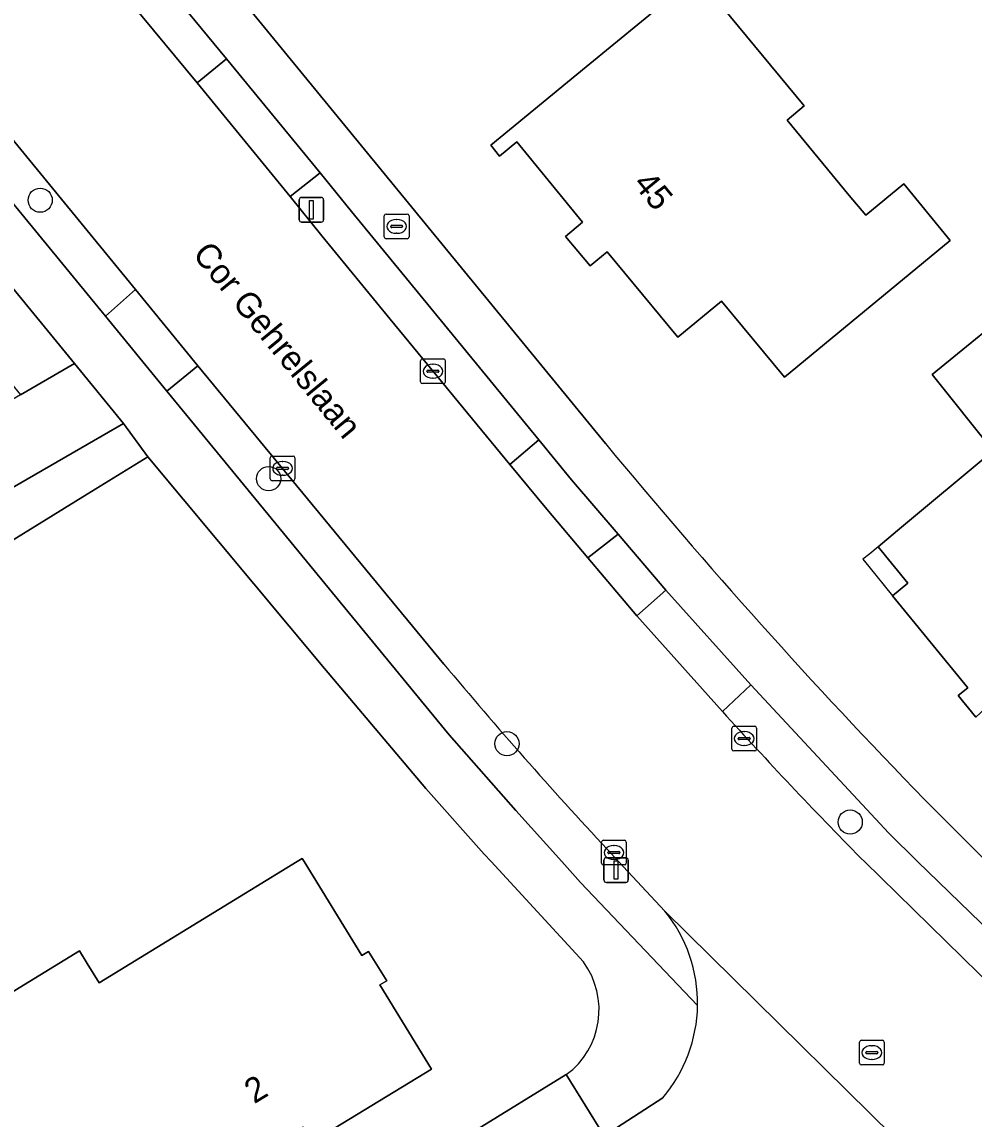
# Model space of a CAD drawing. Extents: x 157320 to 158835, y 386650 to 388491.
# Drawn here: x 157997.35 to 158035.89, y 387239.59 to 387283.97 of the extents above; entities that cross this region are included whole.
import ezdxf

# ---------------------------------------------------------------- set-up
doc = ezdxf.new("R2010")
doc.units = 0
for name, color, linetype in [('IMGEO_Boom', 7, 'Continuous'), ('IMGEO_Brandkraan', 7, 'Continuous'), ('IMGEO_Erf', 7, 'Continuous'), ('IMGEO_Groenvoorziening', 7, 'Continuous'), ('IMGEO_Kolk', 7, 'Continuous'), ('IMGEO_Lichtmast', 7, 'Continuous'), ('IMGEO_Openbare_ruimte_label', 7, 'Continuous'), ('IMGEO_Pand', 7, 'Continuous'), ('IMGEO_Pand_nummerreeks', 7, 'Continuous'), ('IMGEO_Pand_overbouw', 7, 'Continuous'), ('IMGEO_Rijbaan_lokaal_gesloten', 7, 'Continuous'), ('IMGEO_Rioolput', 7, 'Continuous'), ('IMGEO_Voetpad_open', 7, 'Continuous')]:
    doc.layers.add(name, color=color, linetype=linetype)

msp = doc.modelspace()

# ---------------------------------------------------------------- linework, layer by layer
at = {"layer": 'IMGEO_Boom'}
for centre in [(157998.093, 387276.755), (158007.337, 387265.491), (158016.984, 387254.77), (158030.877, 387251.601)]:
    msp.add_circle(centre, 0.489, dxfattribs=at)
at = {"layer": 'IMGEO_Brandkraan'}
for p, q in [((158012.02, 387275.27), (158012.02, 387276.122)), ((158012.095, 387276.196), (158012.947, 387276.196)), ((158012.508, 387275.976), (158012.533, 387275.976)), ((158013.021, 387276.122), (158013.021, 387275.27)), ((158012.279, 387275.69), (158012.279, 387275.702)), ((158012.717, 387275.653), (158012.319, 387275.653)), ((158012.322, 387275.739), (158012.72, 387275.739)), ((158012.763, 387275.702), (158012.763, 387275.69)), ((158012.947, 387275.196), (158012.095, 387275.196)), ((158012.531, 387275.416), (158012.506, 387275.416))]:
    msp.add_line(p, q, dxfattribs=at)
for points in [[(158012.02, 387275.27), (158012.02, 387276.122)], [(158012.095, 387276.196), (158012.947, 387276.196)], [(158013.021, 387276.122), (158013.021, 387275.27)], [(158012.947, 387275.196), (158012.095, 387275.196)]]:
    msp.add_lwpolyline(points, dxfattribs=at)
for centre, radius, start, end in [((158012.097, 387276.12), 0.0765, 91.552, 178.448), ((158012.097, 387276.12), 0.0765, 91.552, 178.448), ((158012.945, 387276.12), 0.0765, 1.552, 88.448), ((158012.945, 387276.12), 0.0765, 1.552, 88.448), ((158012.319, 387275.699), 0.0403, 85.8775, 175.7526), ((158012.316, 387275.689), 0.0366, 178.938, 274.7102), ((158012.72, 387275.696), 0.043, 264.8664, 352.4533), ((158012.724, 387275.701), 0.0386, 1.7309, 96.639), ((158012.097, 387275.272), 0.0765, 181.552, 268.448), ((158012.097, 387275.272), 0.0765, 181.552, 268.448), ((158012.945, 387275.272), 0.0765, 271.552, 358.448), ((158012.945, 387275.272), 0.0765, 271.552, 358.448)]:
    msp.add_arc(centre, radius, start, end, dxfattribs=at)
for centre, major_axis, ratio, start_param, end_param in [((158012.507, 387275.696), (-0.387, 0.002), 0.722429, 4.712389, 7.853982), ((158012.532, 387275.696), (-0.39, 0.002), 0.717154, 1.570796, 4.712389)]:
    msp.add_ellipse(centre, major_axis=major_axis, ratio=ratio, start_param=start_param, end_param=end_param, dxfattribs=at)
at = {"layer": 'IMGEO_Erf'}
for points in [[(157999.612, 387292.962), (158000.785, 387291.532), (158020.97, 387266.911)], [(158020.077, 387245.943), (158016.341, 387250), (158016.061, 387250.304), (158013.703, 387252.963), (158009.6, 387257.817), (158002.445, 387266.373), (158000, 387264.864), (157981.765, 387253.617), (157983.035, 387251.532), (157983.087, 387251.564), (157984.044, 387250), (157994.365, 387233.133)], [(158033.883, 387252.507), (158036.396, 387250)], [(158004.318, 387232.11), (158019.387, 387241.383)]]:
    msp.add_lwpolyline(points, dxfattribs=at)
for points in [[(158028.216, 387269.592), (158025.669, 387272.677), (158023.895, 387271.214), (158021.044, 387274.668), (158020.35, 387274.095), (158019.349, 387275.291), (158020.037, 387275.862), (158017.382, 387279.115), (158016.685, 387278.541), (158016.331, 387278.976), (158020.194, 387282.151), (158024.676, 387285.834), (158029.015, 387280.57), (158028.32, 387279.997), (158030.84, 387276.941), (158031.512, 387276.15), (158033.043, 387277.412), (158034.928, 387275.127)], [(158045.536, 387267.864), (158042.435, 387265.326), (158046.172, 387260.759), (158043.755, 387258.784), (158045.209, 387257.004), (158041.925, 387254.321), (158040.47, 387256.101), (158038.045, 387254.121), (158036.328, 387256.186), (158035.96, 387255.846), (158035.247, 387256.719), (158035.633, 387257.035), (158032.594, 387260.758), (158033.211, 387261.262), (158032.006, 387262.738), (158032.794, 387263.394), (158036.658, 387266.612), (158034.188, 387269.705), (158038.068, 387272.86), (158040.106, 387274.518)], [(157993.419, 387242.559), (157999.689, 387246.391), (158000, 387245.882), (158000.476, 387245.103), (158008.489, 387250), (158008.7, 387250.129), (158008.779, 387250), (158011.111, 387246.203), (158011.384, 387246.371), (158012.116, 387245.178), (158011.843, 387245.01), (158013.935, 387241.6), (158009.103, 387238.662), (158008.74, 387239.261), (158006.646, 387237.988), (158007.009, 387237.389), (158002.664, 387234.747), (158000.614, 387238.055), (158000, 387237.679), (157997.381, 387236.076)]]:
    msp.add_lwpolyline(points, close=True, dxfattribs=at)
for centre, radius, start, end in [((158210.543, 387423.871), 246.118, 219.62353, 224.12811), ((158017.451, 387244.008), 3.262, 306.412, 36.3791)]:
    msp.add_arc(centre, radius, start, end, dxfattribs=at)
at = {"layer": 'IMGEO_Groenvoorziening'}
for points in [[(157946.102, 387338.65), (158000, 387272.965), (158000.735, 387272.069), (158001.953, 387273.145), (158000, 387275.528), (157949.905, 387336.66), (157948.052, 387338.921), (157946.867, 387339.91), (157946.189, 387339.362)], [(157998.976, 387288.125), (158000, 387286.885), (158004.449, 387281.5), (158005.629, 387282.478), (158000, 387289.314), (157997.412, 387292.457)], [(158014.434, 387257.989), (158004.474, 387270.061), (158003.224, 387269.036), (158014.64, 387255.124), (158017.345, 387252.062), (158019.205, 387250), (158019.965, 387249.158), (158024.7, 387244.176)], [(158032.44, 387251.155), (158026.857, 387257.158), (158025.703, 387256.074)], [(158031.312, 387250.14), (158031.451, 387250), (158038.073, 387243.529), (158039.142, 387244.637), (158033.601, 387250), (158032.44, 387251.155)], [(158023.38, 387248.001), (158021.505, 387250), (158021.036, 387250.5)]]:
    msp.add_lwpolyline(points, dxfattribs=at)
for points in [[(157956.447, 387322.693), (157954.567, 387321.043), (157995.369, 387271.233), (157997.295, 387268.882), (157999.484, 387270.155)], [(158012.256, 387271.943), (158017.101, 387266.07), (158018.276, 387267.066), (158013.471, 387272.92), (158010.687, 387276.293), (158009.429, 387277.867), (158008.212, 387276.901), (158009.486, 387275.32)], [(158000, 387264.864), (158002.445, 387266.373), (158001.465, 387267.718), (158000, 387266.873), (157981.182, 387256.016), (157970.793, 387250), (157963.952, 387246.039), (157961.785, 387246.252), (157962.166, 387243.986), (157963.282, 387242.2), (157979.287, 387252.079), (157981.765, 387253.617)], [(158022.244, 387259.949), (158023.416, 387260.98), (158021.481, 387263.247), (158020.261, 387262.291)], [(158005.773, 387229.685), (158020.924, 387238.906), (158019.387, 387241.383), (158004.318, 387232.11)]]:
    msp.add_lwpolyline(points, close=True, dxfattribs=at)
for centre, radius, start, end in [((158161.801, 387381.247), 192.119, 219.90923, 222.88697), ((158166.946, 387383.963), 190.539, 222.15946, 224.615), ((158018.783, 387244.274), 5.918, 359.0489, 39.03)]:
    msp.add_arc(centre, radius, start, end, dxfattribs=at)
at = {"layer": 'IMGEO_Kolk'}
for p, q in [((158013.489, 387269.411), (158013.489, 387270.263)), ((158013.564, 387270.337), (158014.416, 387270.337)), ((158014.49, 387270.263), (158014.49, 387269.411)), ((158013.748, 387269.831), (158013.748, 387269.843)), ((158014.186, 387269.794), (158013.788, 387269.794)), ((158013.791, 387269.88), (158014.189, 387269.88)), ((158013.977, 387270.117), (158014.002, 387270.117)), ((158014.232, 387269.843), (158014.232, 387269.831)), ((158014.416, 387269.337), (158013.564, 387269.337)), ((158014, 387269.557), (158013.975, 387269.557)), ((158007.402, 387265.481), (158007.402, 387266.333)), ((158007.477, 387266.407), (158008.329, 387266.407)), ((158007.89, 387266.187), (158007.915, 387266.187)), ((158008.403, 387266.333), (158008.403, 387265.481)), ((158007.661, 387265.901), (158007.661, 387265.913)), ((158008.099, 387265.864), (158007.701, 387265.864)), ((158007.704, 387265.95), (158008.102, 387265.95)), ((158008.145, 387265.913), (158008.145, 387265.901)), ((158008.329, 387265.407), (158007.477, 387265.407)), ((158007.913, 387265.627), (158007.888, 387265.627)), ((158026.086, 387254.553), (158026.086, 387255.405)), ((158026.161, 387255.479), (158027.013, 387255.479)), ((158026.574, 387255.259), (158026.599, 387255.259)), ((158027.087, 387255.405), (158027.087, 387254.553)), ((158026.345, 387254.973), (158026.345, 387254.985)), ((158026.783, 387254.936), (158026.385, 387254.936)), ((158026.388, 387255.022), (158026.786, 387255.022)), ((158026.597, 387254.699), (158026.572, 387254.699)), ((158026.829, 387254.985), (158026.829, 387254.973)), ((158027.013, 387254.479), (158026.161, 387254.479)), ((158020.814, 387249.941), (158020.814, 387250.793)), ((158020.889, 387250.867), (158021.741, 387250.867)), ((158021.302, 387250.647), (158021.327, 387250.647)), ((158021.815, 387250.793), (158021.815, 387249.941)), ((158021.073, 387250.361), (158021.073, 387250.373)), ((158021.511, 387250.324), (158021.113, 387250.324)), ((158021.116, 387250.41), (158021.514, 387250.41)), ((158021.557, 387250.373), (158021.557, 387250.361)), ((158021.741, 387249.867), (158020.889, 387249.867)), ((158021.325, 387250.087), (158021.3, 387250.087))]:
    msp.add_line(p, q, dxfattribs=at)
for points in [[(158013.489, 387269.411), (158013.489, 387270.263)], [(158013.564, 387270.337), (158014.416, 387270.337)], [(158014.49, 387270.263), (158014.49, 387269.411)], [(158014.416, 387269.337), (158013.564, 387269.337)], [(158007.402, 387265.481), (158007.402, 387266.333)], [(158007.477, 387266.407), (158008.329, 387266.407)], [(158008.403, 387266.333), (158008.403, 387265.481)], [(158008.329, 387265.407), (158007.477, 387265.407)], [(158026.086, 387254.553), (158026.086, 387255.405)], [(158026.161, 387255.479), (158027.013, 387255.479)], [(158027.087, 387255.405), (158027.087, 387254.553)], [(158027.013, 387254.479), (158026.161, 387254.479)], [(158020.814, 387249.941), (158020.814, 387250.793)], [(158020.889, 387250.867), (158021.741, 387250.867)], [(158021.815, 387250.793), (158021.815, 387249.941)], [(158021.741, 387249.867), (158020.889, 387249.867)]]:
    msp.add_lwpolyline(points, dxfattribs=at)
for centre, radius, start, end in [((158013.566, 387270.261), 0.0765, 91.552, 178.448), ((158013.566, 387270.261), 0.0765, 91.552, 178.448), ((158014.414, 387270.261), 0.0765, 1.552, 88.448), ((158014.414, 387270.261), 0.0765, 1.552, 88.448), ((158013.788, 387269.84), 0.0403, 85.8775, 175.7526), ((158013.785, 387269.83), 0.0366, 178.938, 274.7102), ((158014.189, 387269.837), 0.043, 264.8664, 352.4533), ((158014.193, 387269.842), 0.0386, 1.7309, 96.639), ((158013.566, 387269.413), 0.0765, 181.552, 268.448), ((158013.566, 387269.413), 0.0765, 181.552, 268.448), ((158014.414, 387269.413), 0.0765, 271.552, 358.448), ((158014.414, 387269.413), 0.0765, 271.552, 358.448), ((158007.479, 387266.331), 0.0765, 91.552, 178.448), ((158007.479, 387266.331), 0.0765, 91.552, 178.448), ((158008.327, 387266.331), 0.0765, 1.552, 88.448), ((158008.327, 387266.331), 0.0765, 1.552, 88.448), ((158007.701, 387265.91), 0.0403, 85.8775, 175.7526), ((158007.698, 387265.9), 0.0366, 178.938, 274.7102), ((158008.102, 387265.907), 0.043, 264.8664, 352.4533), ((158008.106, 387265.912), 0.0386, 1.7309, 96.639), ((158007.479, 387265.483), 0.0765, 181.552, 268.448), ((158007.479, 387265.483), 0.0765, 181.552, 268.448), ((158008.327, 387265.483), 0.0765, 271.552, 358.448), ((158008.327, 387265.483), 0.0765, 271.552, 358.448), ((158026.163, 387255.403), 0.0765, 91.552, 178.448), ((158026.163, 387255.403), 0.0765, 91.552, 178.448), ((158027.011, 387255.403), 0.0765, 1.552, 88.448), ((158027.011, 387255.403), 0.0765, 1.552, 88.448), ((158026.385, 387254.982), 0.0403, 85.8775, 175.7526), ((158026.382, 387254.972), 0.0366, 178.938, 274.7102), ((158026.786, 387254.979), 0.043, 264.8664, 352.4533), ((158026.79, 387254.984), 0.0386, 1.7309, 96.639), ((158026.163, 387254.555), 0.0765, 181.552, 268.448), ((158026.163, 387254.555), 0.0765, 181.552, 268.448), ((158027.011, 387254.555), 0.0765, 271.552, 358.448), ((158027.011, 387254.555), 0.0765, 271.552, 358.448), ((158020.891, 387250.791), 0.0765, 91.552, 178.448), ((158020.891, 387250.791), 0.0765, 91.552, 178.448), ((158021.739, 387250.791), 0.0765, 1.552, 88.448), ((158021.739, 387250.791), 0.0765, 1.552, 88.448), ((158021.113, 387250.37), 0.0403, 85.8775, 175.7526), ((158021.11, 387250.36), 0.0366, 178.938, 274.7102), ((158021.514, 387250.367), 0.043, 264.8664, 352.4533), ((158021.518, 387250.372), 0.0386, 1.7309, 96.639), ((158020.891, 387249.943), 0.0765, 181.552, 268.448), ((158020.891, 387249.943), 0.0765, 181.552, 268.448), ((158021.739, 387249.943), 0.0765, 271.552, 358.448), ((158021.739, 387249.943), 0.0765, 271.552, 358.448)]:
    msp.add_arc(centre, radius, start, end, dxfattribs=at)
for centre, major_axis, ratio, start_param, end_param in [((158013.976, 387269.837), (-0.387, 0.002), 0.722429, 4.712389, 7.853982), ((158014.001, 387269.837), (-0.39, 0.002), 0.717154, 1.570796, 4.712389), ((158007.889, 387265.907), (-0.387, 0.002), 0.722429, 4.712389, 7.853982), ((158007.914, 387265.907), (-0.39, 0.002), 0.717154, 1.570796, 4.712389), ((158026.573, 387254.979), (-0.387, 0.002), 0.722429, 4.712389, 7.853982), ((158026.598, 387254.979), (-0.39, 0.002), 0.717154, 1.570796, 4.712389), ((158021.301, 387250.367), (-0.387, 0.002), 0.722429, 4.712389, 7.853982), ((158021.326, 387250.367), (-0.39, 0.002), 0.717154, 1.570796, 4.712389)]:
    msp.add_ellipse(centre, major_axis=major_axis, ratio=ratio, start_param=start_param, end_param=end_param, dxfattribs=at)
at = {"layer": 'IMGEO_Lichtmast'}
for p, q in [((158008.675, 387276.866), (158009.465, 387276.866)), ((158009.465, 387276.866), (158008.675, 387276.866)), ((158008.575, 387275.966), (158008.575, 387276.766)), ((158008.575, 387276.766), (158008.575, 387275.966)), ((158009.565, 387276.766), (158009.565, 387275.966)), ((158009.565, 387275.966), (158009.565, 387276.766)), ((158009.465, 387275.866), (158008.675, 387275.866)), ((158008.675, 387275.866), (158009.465, 387275.866)), ((158021.007, 387250.16), (158021.797, 387250.16)), ((158021.797, 387250.16), (158021.007, 387250.16)), ((158020.907, 387249.26), (158020.907, 387250.06)), ((158020.907, 387250.06), (158020.907, 387249.26)), ((158021.897, 387250.06), (158021.897, 387249.26)), ((158021.897, 387249.26), (158021.897, 387250.06)), ((158021.797, 387249.16), (158021.007, 387249.16)), ((158021.007, 387249.16), (158021.797, 387249.16))]:
    msp.add_line(p, q, dxfattribs=at)
for points in [[(158008.995, 387276.741), (158009.145, 387276.741), (158009.145, 387275.991), (158008.995, 387275.991), (158008.995, 387276.741)], [(158021.327, 387250.035), (158021.477, 387250.035), (158021.477, 387249.285), (158021.327, 387249.285), (158021.327, 387250.035)]]:
    msp.add_lwpolyline(points, dxfattribs=at)
for centre, start, end in [((158008.675, 387276.766), 90, 180), ((158008.675, 387276.766), 90, 180), ((158009.465, 387276.766), 0, 90), ((158009.465, 387276.766), 360, 90), ((158008.675, 387275.966), 180, 270), ((158008.675, 387275.966), 180, 270), ((158009.465, 387275.966), 270, 0), ((158009.465, 387275.966), 270, 0), ((158021.007, 387250.06), 90, 180), ((158021.007, 387250.06), 90, 180), ((158021.797, 387250.06), 0, 90), ((158021.797, 387250.06), 360, 90), ((158021.007, 387249.26), 180, 270), ((158021.007, 387249.26), 180, 270), ((158021.797, 387249.26), 270, 0), ((158021.797, 387249.26), 270, 0)]:
    msp.add_arc(centre, 0.1, start, end, dxfattribs=at)
at = {"layer": 'IMGEO_Pand'}
for points in [[(158030.84, 387276.941), (158028.32, 387279.997), (158029.015, 387280.57), (158024.676, 387285.834), (158020.194, 387282.151), (158016.331, 387278.976), (158016.685, 387278.541), (158017.382, 387279.115), (158020.037, 387275.862), (158019.349, 387275.291), (158020.35, 387274.095), (158021.044, 387274.668), (158023.895, 387271.214), (158025.669, 387272.677), (158028.216, 387269.592), (158034.928, 387275.127), (158033.043, 387277.412), (158031.512, 387276.15)], [(158045.209, 387257.004), (158043.755, 387258.784), (158046.172, 387260.759), (158042.435, 387265.326), (158045.536, 387267.864), (158040.106, 387274.518), (158038.068, 387272.86), (158034.188, 387269.705), (158036.658, 387266.612), (158032.794, 387263.394), (158032.006, 387262.738), (158033.211, 387261.262), (158032.594, 387260.758), (158035.633, 387257.035), (158035.247, 387256.719), (158035.96, 387255.846), (158036.328, 387256.186), (158038.045, 387254.121), (158040.47, 387256.101), (158041.925, 387254.321)], [(158007.009, 387237.389), (158006.646, 387237.988), (158008.74, 387239.261), (158009.103, 387238.662), (158013.935, 387241.6), (158011.843, 387245.01), (158012.116, 387245.178), (158011.384, 387246.371), (158011.111, 387246.203), (158008.779, 387250), (158008.7, 387250.129), (158008.489, 387250), (158000.476, 387245.103), (158000, 387245.882), (157999.689, 387246.391), (157993.419, 387242.559), (157997.381, 387236.076), (158000, 387237.679), (158000.614, 387238.055), (158002.664, 387234.747)]]:
    msp.add_lwpolyline(points, close=True, dxfattribs=at)
at = {"layer": 'IMGEO_Pand_overbouw'}
msp.add_lwpolyline([(158032.594, 387260.758), (158033.211, 387261.262), (158032.006, 387262.738), (158031.668, 387262.457), (158031.392, 387262.235), (158031.63, 387261.939)], close=True, dxfattribs=at)
at = {"layer": 'IMGEO_Rijbaan_lokaal_gesloten'}
for points in [[(157949.905, 387336.66), (158000, 387275.528), (158001.953, 387273.145), (158004.474, 387270.061), (158014.434, 387257.989)], [(158025.703, 387256.074), (158022.244, 387259.949), (158020.261, 387262.291), (158018.597, 387264.257), (158017.101, 387266.07), (158012.256, 387271.943), (158009.486, 387275.32), (158008.212, 387276.901), (158004.449, 387281.5), (158000, 387286.885)], [(158021.036, 387250.5), (158021.505, 387250), (158023.38, 387248.001), (158035.364, 387236.182), (158039.205, 387232.702), (158042.245, 387230.038)], [(158040.708, 387241.061), (158038.073, 387243.529), (158031.451, 387250), (158031.312, 387250.14)], [(158035.364, 387236.182), (158023.38, 387248.001)], [(158023.291, 387240.449), (158020.924, 387238.906), (158005.773, 387229.685), (158002.063, 387227.435), (158000, 387226.184), (157998.983, 387225.567), (157998.159, 387225.068), (157994.11, 387222.595), (157978.682, 387213.184), (157976.05, 387211.578), (157976.178, 387211.336), (157973.945, 387209.978), (157973.803, 387210.247), (157972.463, 387209.428), (157971.902, 387209.086), (157977.357, 387199.024)]]:
    msp.add_lwpolyline(points, dxfattribs=at)
for centre, radius, start, end in [((158161.801, 387381.247), 192.119, 219.90923, 222.88697), ((158166.946, 387383.963), 190.539, 222.15946, 224.615), ((158018.783, 387244.274), 5.918, 359.0489, 39.03), ((158018.791, 387244.28), 5.91, 319.5903, 358.9913)]:
    msp.add_arc(centre, radius, start, end, dxfattribs=at)
at = {"layer": 'IMGEO_Rioolput'}
for p, q in [((158031.254, 387241.848), (158031.254, 387242.7)), ((158031.329, 387242.774), (158032.181, 387242.774)), ((158032.255, 387242.7), (158032.255, 387241.848)), ((158031.513, 387242.268), (158031.513, 387242.28)), ((158031.951, 387242.231), (158031.553, 387242.231)), ((158031.556, 387242.317), (158031.954, 387242.317)), ((158031.742, 387242.554), (158031.767, 387242.554)), ((158031.997, 387242.28), (158031.997, 387242.268)), ((158032.181, 387241.774), (158031.329, 387241.774)), ((158031.765, 387241.994), (158031.74, 387241.994))]:
    msp.add_line(p, q, dxfattribs=at)
for points in [[(158031.254, 387241.848), (158031.254, 387242.7)], [(158031.329, 387242.774), (158032.181, 387242.774)], [(158032.255, 387242.7), (158032.255, 387241.848)], [(158032.181, 387241.774), (158031.329, 387241.774)]]:
    msp.add_lwpolyline(points, dxfattribs=at)
for centre, radius, start, end in [((158031.331, 387242.698), 0.0765, 91.552, 178.448), ((158031.331, 387242.698), 0.0765, 91.552, 178.448), ((158032.179, 387242.698), 0.0765, 1.552, 88.448), ((158032.179, 387242.698), 0.0765, 1.552, 88.448), ((158031.553, 387242.277), 0.0403, 85.8775, 175.7526), ((158031.55, 387242.267), 0.0366, 178.938, 274.7102), ((158031.954, 387242.274), 0.043, 264.8664, 352.4533), ((158031.958, 387242.279), 0.0386, 1.7309, 96.639), ((158031.331, 387241.85), 0.0765, 181.552, 268.448), ((158031.331, 387241.85), 0.0765, 181.552, 268.448), ((158032.179, 387241.85), 0.0765, 271.552, 358.448), ((158032.179, 387241.85), 0.0765, 271.552, 358.448)]:
    msp.add_arc(centre, radius, start, end, dxfattribs=at)
for centre, major_axis, ratio, start_param, end_param in [((158031.741, 387242.274), (-0.387, 0.002), 0.722429, 4.712389, 7.853982), ((158031.766, 387242.274), (-0.39, 0.002), 0.717154, 1.570796, 4.712389)]:
    msp.add_ellipse(centre, major_axis=major_axis, ratio=ratio, start_param=start_param, end_param=end_param, dxfattribs=at)
at = {"layer": 'IMGEO_Voetpad_open'}
for points in [[(158024.7, 387244.176), (158019.965, 387249.158), (158019.205, 387250), (158017.345, 387252.062), (158014.64, 387255.124), (158003.224, 387269.036), (158000.735, 387272.069), (158000, 387272.965), (157946.102, 387338.65)], [(157946.913, 387334.332), (157956.447, 387322.693), (157999.484, 387270.155), (158001.465, 387267.718), (158002.445, 387266.373), (158009.6, 387257.817), (158013.703, 387252.963), (158016.061, 387250.304), (158016.341, 387250), (158020.077, 387245.943)], [(158020.97, 387266.911), (158000.785, 387291.532), (157999.612, 387292.962), (157998.133, 387294.766)], [(157997.412, 387292.457), (158000, 387289.314), (158005.629, 387282.478), (158009.429, 387277.867), (158010.687, 387276.293), (158013.471, 387272.92), (158018.276, 387267.066), (158019.602, 387265.45), (158021.481, 387263.247), (158023.416, 387260.98), (158026.857, 387257.158), (158032.44, 387251.155), (158033.601, 387250), (158039.142, 387244.637), (158041.758, 387242.201), (158047.632, 387236.932)], [(157981.093, 387261.971), (157973.066, 387275.17), (157970.437, 387273.719), (157972.058, 387271.069), (157980.188, 387257.732), (157981.182, 387256.016), (158000, 387266.873)], [(158000, 387266.873), (158001.465, 387267.718), (157999.484, 387270.155), (157997.295, 387268.882), (157983.793, 387261.027)], [(158036.396, 387250), (158033.883, 387252.507)], [(158019.387, 387241.383), (158020.924, 387238.906), (158023.291, 387240.449)]]:
    msp.add_lwpolyline(points, dxfattribs=at)
for points in [[(158009.429, 387277.867), (158005.629, 387282.478), (158004.449, 387281.5), (158008.212, 387276.901)], [(158004.474, 387270.061), (158001.953, 387273.145), (158000.735, 387272.069), (158003.224, 387269.036)], [(158018.276, 387267.066), (158017.101, 387266.07), (158018.597, 387264.257), (158020.261, 387262.291), (158021.481, 387263.247), (158019.602, 387265.45)], [(158023.416, 387260.98), (158022.244, 387259.949), (158025.703, 387256.074), (158026.857, 387257.158)]]:
    msp.add_lwpolyline(points, close=True, dxfattribs=at)
for centre, radius, start, end in [((158210.543, 387423.871), 246.118, 219.62353, 224.12811), ((158017.451, 387244.008), 3.262, 306.412, 36.3791), ((158018.791, 387244.28), 5.91, 319.5903, 358.9913)]:
    msp.add_arc(centre, radius, start, end, dxfattribs=at)

# ---------------------------------------------------------------- texts
at = {"layer": 'IMGEO_Openbare_ruimte_label'}
msp.add_text('Cor Gehrelslaan', height=1, rotation=309.358, dxfattribs=at).set_placement((158004.224, 387274.554))
at = {"layer": 'IMGEO_Pand_nummerreeks'}
for s, rotation, p in [('45', 309.4995, (158022.057, 387277.405)), ('2', 31.3005, (158006.754, 387240.182))]:
    msp.add_text(s, height=1, rotation=rotation, dxfattribs=at).set_placement(p)

doc.saveas('drawing.dxf')
